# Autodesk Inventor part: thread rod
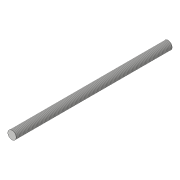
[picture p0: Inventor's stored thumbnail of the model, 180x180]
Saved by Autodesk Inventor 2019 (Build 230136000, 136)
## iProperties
Created: 2019-11
Part Number: thread rod
Material: Generic
Document SubType Name: Sheet Metal
Designer: Hp
Density: 1 g/cm^3
Sheet Metal Rule: Default_mm
Appearance: Default
Author: Hp
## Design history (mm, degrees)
sketch "Sketch1"
  geometry: C1 r 4 at (0, 0); 1 further point
  constraints: 1 centre point, 1 coincident
  dimensions: "d0" = 8 diameter of C1
extrude "Extrusion1" new body sketch "Sketch1" distance "d1" = 150; taper "d2" = 0 deg
thread "Thread1" dims "d3" = 10, "d4" = 0
body "Solid1"
other parameters: "Thickness" = 0.5, "BendRadius" = 0.5 (= Thickness), "BendReliefWidth" = 0.5 (= Thickness), "BendReliefDepth" = 0.25 (= 0.5 x Thickness), "CornerReliefSize" = 2 (= 4 x Thickness), "SeamGap" = 0.01, "MinimumRemnant" = 1 (= 2 x Thickness), "TransitionRadius" = 0.5 (= BendRadius), "JacobiRadiusSize" = 0.5 (= BendRadius), "GapSize" = 0.5 (= Thickness)
